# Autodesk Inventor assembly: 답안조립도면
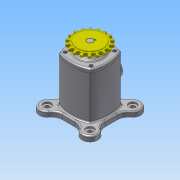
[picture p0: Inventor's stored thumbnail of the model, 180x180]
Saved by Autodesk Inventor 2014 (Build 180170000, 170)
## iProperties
Created: 2016-05
Part Number: 답안조립도면
Document SubType Name: Assembly
Designer: 703-04
Author: 703-04
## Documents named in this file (9)
- C:\Users\703-04\Desktop\460508V1010\답안조립도면.iam
- C:\Users\703-04\Desktop\460508V1010\본체.ipt
- C:\Users\703-04\Desktop\460508V1010\편심축.ipt
- C:\Users\703-04\Desktop\460508V1010\스프로킷.ipt
- C:\Users\703-04\Desktop\460508V1010\키5x5.ipt
- C:\Users\703-04\Desktop\460508V1010\오일실.ipt
- C:\Users\703-04\Desktop\460508V1010\커버.ipt
- C:\Users\703-04\Desktop\460508V1010\베어링-6203.ipt
- C:\Users\703-04\Desktop\460508V1010\M4x0.7x12.ipt
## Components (8 placed, 1 different names)
1. M4x0.7x12:5
2. M4x0.7x12:9
3. M4x0.7x12:10
4. M4x0.7x12:11
5. M4x0.7x12:3
6. M4x0.7x12:12
7. M4x0.7x12:13
8. M4x0.7x12:14
